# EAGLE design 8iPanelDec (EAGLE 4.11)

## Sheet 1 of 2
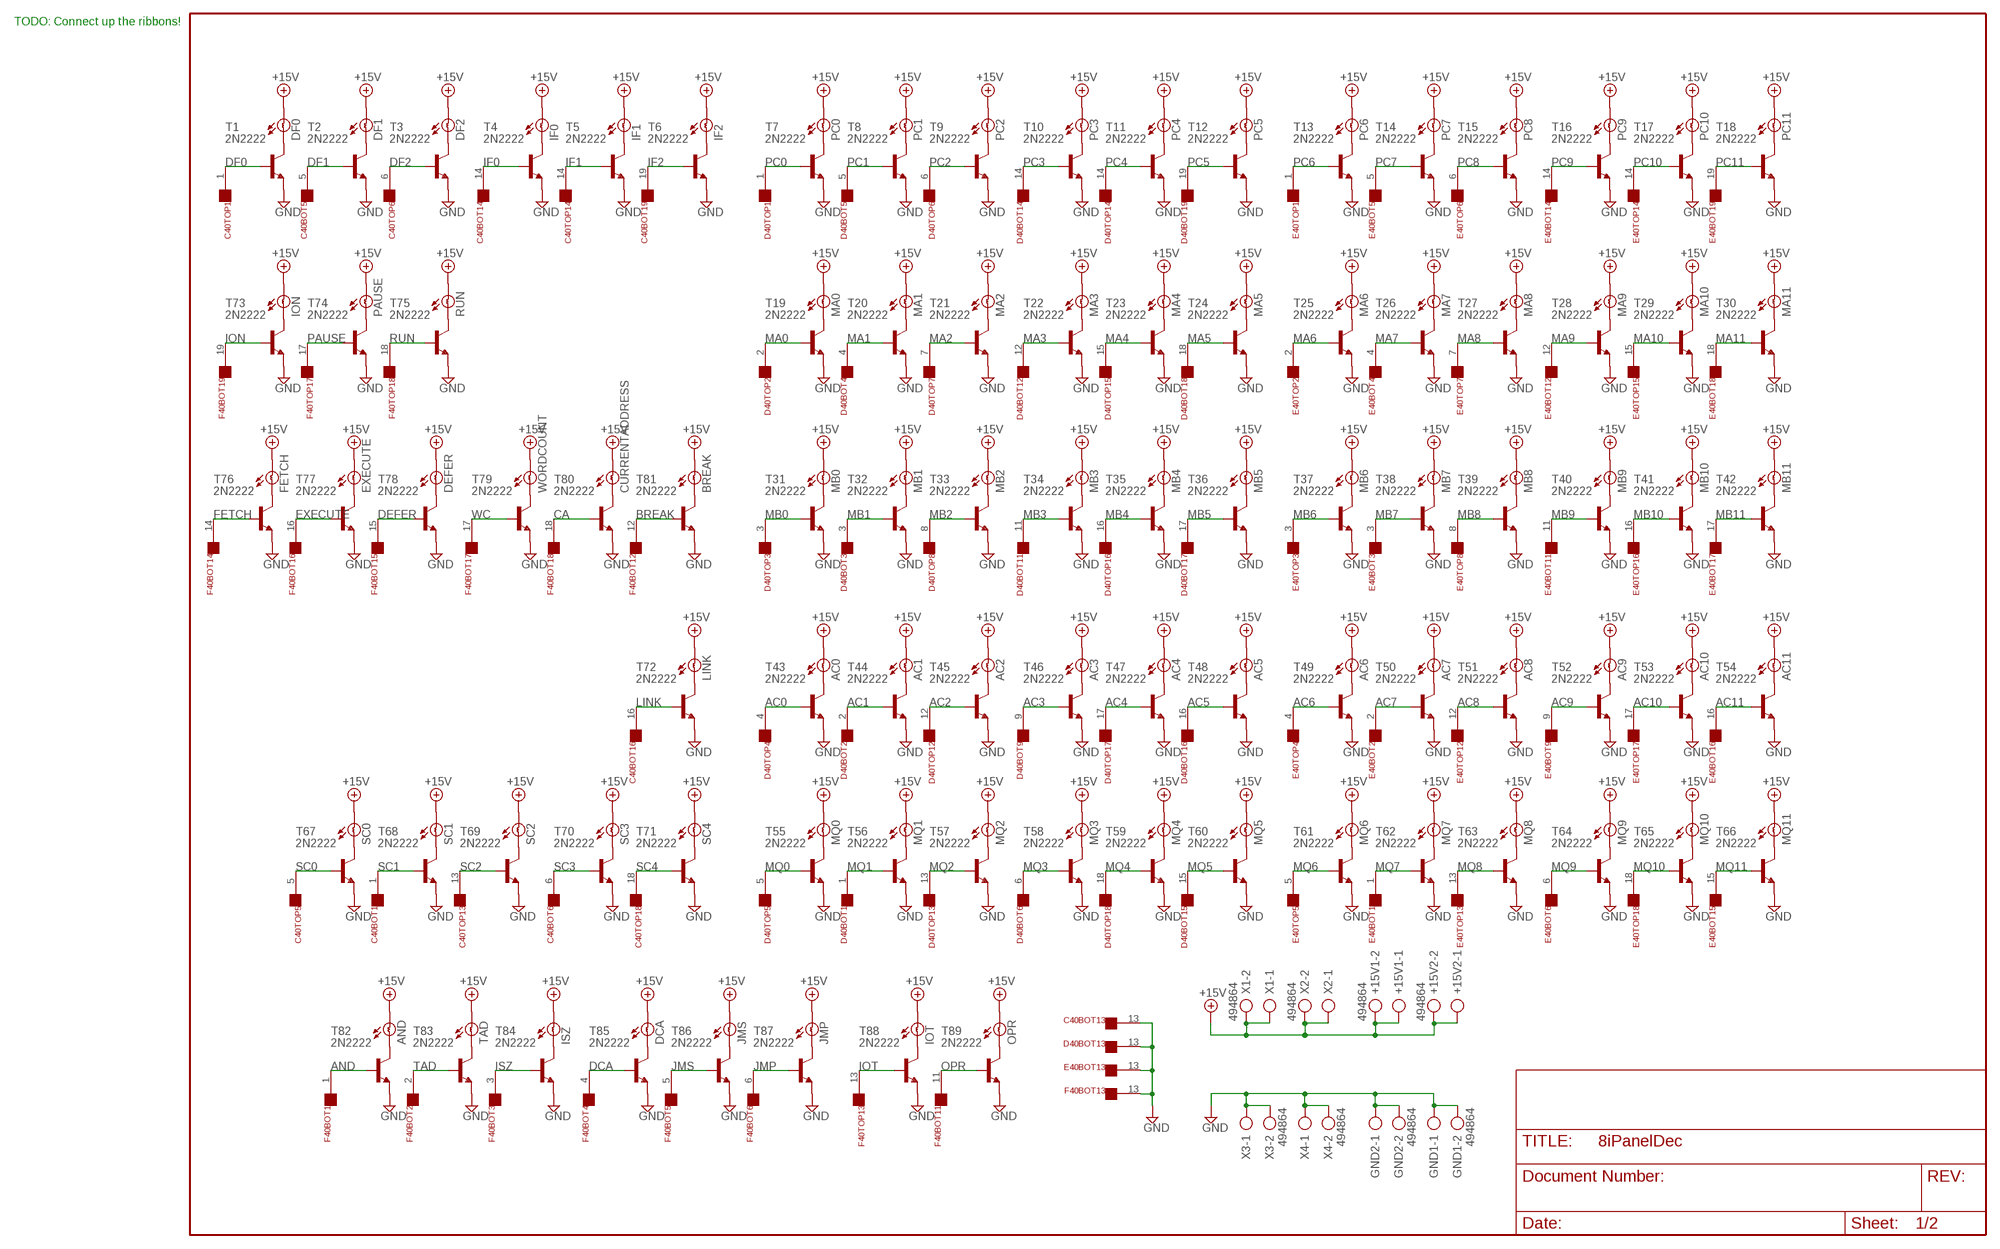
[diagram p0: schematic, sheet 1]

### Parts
+15V1  494864  AK500/2  [AK500/2]
+15V2  494864  AK500/2  [AK500/2]
AC0  BULB  [BULB]
AC1  BULB  [BULB]
AC2  BULB  [BULB]
AC3  BULB  [BULB]
AC4  BULB  [BULB]
AC5  BULB  [BULB]
AC6  BULB  [BULB]
AC7  BULB  [BULB]
AC8  BULB  [BULB]
AC9  BULB  [BULB]
AC10  BULB  [BULB]
AC11  BULB  [BULB]
AND  BULB  [BULB]
BREAK  BULB  [BULB]
C40BOT  FLEX19  [FLEX19]
C40TOP  FLEX19  [FLEX19]
CURRENTADDRESS  BULB  [BULB]
D40BOT  FLEX19  [FLEX19]
D40TOP  FLEX19  [FLEX19]
DCA  BULB  [BULB]
DEFER  BULB  [BULB]
DF0  BULB  [BULB]
DF1  BULB  [BULB]
DF2  BULB  [BULB]
E40BOT  FLEX19  [FLEX19]
E40TOP  FLEX19  [FLEX19]
EXECUTE  BULB  [BULB]
F40BOT  FLEX19  [FLEX19]
F40TOP  FLEX19  [FLEX19]
FETCH  BULB  [BULB]
GND1  494864  AK500/2  [AK500/2]
GND2  494864  AK500/2  [AK500/2]
IF0  BULB  [BULB]
IF1  BULB  [BULB]
IF2  BULB  [BULB]
ION  BULB  [BULB]
IOT  BULB  [BULB]
ISZ  BULB  [BULB]
JMP  BULB  [BULB]
JMS  BULB  [BULB]
LINK  BULB  [BULB]
MA0  BULB  [BULB]
MA1  BULB  [BULB]
MA2  BULB  [BULB]
MA3  BULB  [BULB]
MA4  BULB  [BULB]
MA5  BULB  [BULB]
MA6  BULB  [BULB]
MA7  BULB  [BULB]
MA8  BULB  [BULB]
MA9  BULB  [BULB]
MA10  BULB  [BULB]
MA11  BULB  [BULB]
MB0  BULB  [BULB]
MB1  BULB  [BULB]
MB2  BULB  [BULB]
MB3  BULB  [BULB]
MB4  BULB  [BULB]
MB5  BULB  [BULB]
MB6  BULB  [BULB]
MB7  BULB  [BULB]
MB8  BULB  [BULB]
MB9  BULB  [BULB]
MB10  BULB  [BULB]
MB11  BULB  [BULB]
MQ0  BULB  [BULB]
MQ1  BULB  [BULB]
MQ2  BULB  [BULB]
MQ3  BULB  [BULB]
MQ4  BULB  [BULB]
MQ5  BULB  [BULB]
MQ6  BULB  [BULB]
MQ7  BULB  [BULB]
MQ8  BULB  [BULB]
MQ9  BULB  [BULB]
MQ10  BULB  [BULB]
MQ11  BULB  [BULB]
OPR  BULB  [BULB]
PAUSE  BULB  [BULB]
PC0  BULB  [BULB]
PC1  BULB  [BULB]
PC2  BULB  [BULB]
PC3  BULB  [BULB]
PC4  BULB  [BULB]
PC5  BULB  [BULB]
PC6  BULB  [BULB]
PC7  BULB  [BULB]
PC8  BULB  [BULB]
PC9  BULB  [BULB]
PC10  BULB  [BULB]
PC11  BULB  [BULB]
RUN  BULB  [BULB]
SC0  BULB  [BULB]
SC1  BULB  [BULB]
SC2  BULB  [BULB]
SC3  BULB  [BULB]
SC4  BULB  [BULB]
T1  2N2222  -NPN-TO92  [TO92]
T2  2N2222  -NPN-TO92  [TO92]
T3  2N2222  -NPN-TO92  [TO92]
T4  2N2222  -NPN-TO92  [TO92]
T5  2N2222  -NPN-TO92  [TO92]
T6  2N2222  -NPN-TO92  [TO92]
T7  2N2222  -NPN-TO92  [TO92]
T8  2N2222  -NPN-TO92  [TO92]
T9  2N2222  -NPN-TO92  [TO92]
T10  2N2222  -NPN-TO92  [TO92]
T11  2N2222  -NPN-TO92  [TO92]
T12  2N2222  -NPN-TO92  [TO92]
T13  2N2222  -NPN-TO92  [TO92]
T14  2N2222  -NPN-TO92  [TO92]
T15  2N2222  -NPN-TO92  [TO92]
T16  2N2222  -NPN-TO92  [TO92]
T17  2N2222  -NPN-TO92  [TO92]
T18  2N2222  -NPN-TO92  [TO92]
T19  2N2222  -NPN-TO92  [TO92]
T20  2N2222  -NPN-TO92  [TO92]
T21  2N2222  -NPN-TO92  [TO92]
T22  2N2222  -NPN-TO92  [TO92]
T23  2N2222  -NPN-TO92  [TO92]
T24  2N2222  -NPN-TO92  [TO92]
T25  2N2222  -NPN-TO92  [TO92]
T26  2N2222  -NPN-TO92  [TO92]
T27  2N2222  -NPN-TO92  [TO92]
T28  2N2222  -NPN-TO92  [TO92]
T29  2N2222  -NPN-TO92  [TO92]
T30  2N2222  -NPN-TO92  [TO92]
T31  2N2222  -NPN-TO92  [TO92]
T32  2N2222  -NPN-TO92  [TO92]
T33  2N2222  -NPN-TO92  [TO92]
T34  2N2222  -NPN-TO92  [TO92]
T35  2N2222  -NPN-TO92  [TO92]
T36  2N2222  -NPN-TO92  [TO92]
T37  2N2222  -NPN-TO92  [TO92]
T38  2N2222  -NPN-TO92  [TO92]
T39  2N2222  -NPN-TO92  [TO92]
T40  2N2222  -NPN-TO92  [TO92]
T41  2N2222  -NPN-TO92  [TO92]
T42  2N2222  -NPN-TO92  [TO92]
T43  2N2222  -NPN-TO92  [TO92]
T44  2N2222  -NPN-TO92  [TO92]
T45  2N2222  -NPN-TO92  [TO92]
T46  2N2222  -NPN-TO92  [TO92]
T47  2N2222  -NPN-TO92  [TO92]
T48  2N2222  -NPN-TO92  [TO92]
T49  2N2222  -NPN-TO92  [TO92]
T50  2N2222  -NPN-TO92  [TO92]
T51  2N2222  -NPN-TO92  [TO92]
T52  2N2222  -NPN-TO92  [TO92]
T53  2N2222  -NPN-TO92  [TO92]
T54  2N2222  -NPN-TO92  [TO92]
T55  2N2222  -NPN-TO92  [TO92]
T56  2N2222  -NPN-TO92  [TO92]
T57  2N2222  -NPN-TO92  [TO92]
T58  2N2222  -NPN-TO92  [TO92]
T59  2N2222  -NPN-TO92  [TO92]
T60  2N2222  -NPN-TO92  [TO92]
T61  2N2222  -NPN-TO92  [TO92]
T62  2N2222  -NPN-TO92  [TO92]
T63  2N2222  -NPN-TO92  [TO92]
T64  2N2222  -NPN-TO92  [TO92]
T65  2N2222  -NPN-TO92  [TO92]
T66  2N2222  -NPN-TO92  [TO92]
T67  2N2222  -NPN-TO92  [TO92]
T68  2N2222  -NPN-TO92  [TO92]
T69  2N2222  -NPN-TO92  [TO92]
T70  2N2222  -NPN-TO92  [TO92]
T71  2N2222  -NPN-TO92  [TO92]
T72  2N2222  -NPN-TO92  [TO92]
T73  2N2222  -NPN-TO92  [TO92]
T74  2N2222  -NPN-TO92  [TO92]
T75  2N2222  -NPN-TO92  [TO92]
T76  2N2222  -NPN-TO92  [TO92]
T77  2N2222  -NPN-TO92  [TO92]
T78  2N2222  -NPN-TO92  [TO92]
T79  2N2222  -NPN-TO92  [TO92]
T80  2N2222  -NPN-TO92  [TO92]
T81  2N2222  -NPN-TO92  [TO92]
T82  2N2222  -NPN-TO92  [TO92]
T83  2N2222  -NPN-TO92  [TO92]
T84  2N2222  -NPN-TO92  [TO92]
T85  2N2222  -NPN-TO92  [TO92]
T86  2N2222  -NPN-TO92  [TO92]
T87  2N2222  -NPN-TO92  [TO92]
T88  2N2222  -NPN-TO92  [TO92]
T89  2N2222  -NPN-TO92  [TO92]
TAD  BULB  [BULB]
WORDCOUNT  BULB  [BULB]
X1  494864  AK500/2  [AK500/2]
X2  494864  AK500/2  [AK500/2]
X3  494864  AK500/2  [AK500/2]
X4  494864  AK500/2  [AK500/2]

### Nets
+15V [supply]: +15V1.1 +15V1.2 +15V2.1 +15V2.2 AC0.A AC1.A AC2.A AC3.A AC4.A AC5.A AC6.A AC7.A AC8.A AC9.A AC10.A AC11.A AND.A BREAK.A CURRENTADDRESS.A DCA.A DEFER.A DF0.A DF1.A DF2.A EXECUTE.A FETCH.A IF0.A IF1.A IF2.A ION.A IOT.A ISZ.A JMP.A JMS.A LINK.A MA0.A MA1.A MA2.A MA3.A MA4.A MA5.A MA6.A MA7.A MA8.A MA9.A MA10.A MA11.A MB0.A MB1.A MB2.A MB3.A MB4.A MB5.A MB6.A MB7.A MB8.A MB9.A MB10.A MB11.A MQ0.A MQ1.A MQ2.A MQ3.A MQ4.A MQ5.A MQ6.A MQ7.A MQ8.A MQ9.A MQ10.A MQ11.A OPR.A PAUSE.A PC0.A PC1.A PC2.A PC3.A PC4.A PC5.A PC6.A PC7.A PC8.A PC9.A PC10.A PC11.A RUN.A SC0.A SC1.A SC2.A SC3.A SC4.A TAD.A WORDCOUNT.A X1.1 X1.2 X2.1 X2.2
AC0: D40TOP.4 T43.2(B)
AC1: D40BOT.2 T44.2(B)
AC2: D40TOP.12 T45.2(B)
AC3: D40BOT.9 T46.2(B)
AC4: D40TOP.17 T47.2(B)
AC5: D40BOT.16 T48.2(B)
AC6: E40TOP.4 T49.2(B)
AC7: E40BOT.2 T50.2(B)
AC8: E40TOP.12 T51.2(B)
AC9: E40BOT.9 T52.2(B)
AC10: E40TOP.17 T53.2(B)
AC11: E40BOT.16 T54.2(B)
AND: F40BOT.1 T82.2(B)
BREAK: F40BOT.12 T81.2(B)
CA: F40BOT.18 T80.2(B)
DCA: F40BOT.4 T85.2(B)
DEFER: F40BOT.15 T78.2(B)
DF0: C40TOP.1 T1.2(B)
DF1: C40BOT.5 T2.2(B)
DF2: C40TOP.6 T3.2(B)
EXECUTE: F40BOT.16 T77.2(B)
FETCH: F40BOT.14 T76.2(B)
GND [supply]: C40BOT.13 D40BOT.13 E40BOT.13 F40BOT.13 GND1.1 GND1.2 GND2.1 GND2.2 T1.1(E) T2.1(E) T3.1(E) T4.1(E) T5.1(E) T6.1(E) T7.1(E) T8.1(E) T9.1(E) T10.1(E) T11.1(E) T12.1(E) T13.1(E) T14.1(E) T15.1(E) T16.1(E) T17.1(E) T18.1(E) T19.1(E) T20.1(E) T21.1(E) T22.1(E) T23.1(E) T24.1(E) T25.1(E) T26.1(E) T27.1(E) T28.1(E) T29.1(E) T30.1(E) T31.1(E) T32.1(E) T33.1(E) T34.1(E) T35.1(E) T36.1(E) T37.1(E) T38.1(E) T39.1(E) T40.1(E) T41.1(E) T42.1(E) T43.1(E) T44.1(E) T45.1(E) T46.1(E) T47.1(E) T48.1(E) T49.1(E) T50.1(E) T51.1(E) T52.1(E) T53.1(E) T54.1(E) T55.1(E) T56.1(E) T57.1(E) T58.1(E) T59.1(E) T60.1(E) T61.1(E) T62.1(E) T63.1(E) T64.1(E) T65.1(E) T66.1(E) T67.1(E) T68.1(E) T69.1(E) T70.1(E) T71.1(E) T72.1(E) T73.1(E) T74.1(E) T75.1(E) T76.1(E) T77.1(E) T78.1(E) T79.1(E) T80.1(E) T81.1(E) T82.1(E) T83.1(E) T84.1(E) T85.1(E) T86.1(E) T87.1(E) T88.1(E) T89.1(E) X3.1 X3.2 X4.1 X4.2
IF0: C40BOT.14 T4.2(B)
IF1: C40TOP.14 T5.2(B)
IF2: C40BOT.19 T6.2(B)
ION: F40BOT.19 T73.2(B)
IOT: F40TOP.13 T88.2(B)
ISZ: F40BOT.3 T84.2(B)
JMP: F40BOT.6 T87.2(B)
JMS: F40BOT.5 T86.2(B)
LINK: C40BOT.16 T72.2(B)
MA0: D40TOP.2 T19.2(B)
MA1: D40BOT.4 T20.2(B)
MA2: D40TOP.7 T21.2(B)
MA3: D40BOT.12 T22.2(B)
MA4: D40TOP.15 T23.2(B)
MA5: D40BOT.18 T24.2(B)
MA6: E40TOP.2 T25.2(B)
MA7: E40BOT.4 T26.2(B)
MA8: E40TOP.7 T27.2(B)
MA9: E40BOT.12 T28.2(B)
MA10: E40TOP.15 T29.2(B)
MA11: E40BOT.18 T30.2(B)
MB0: D40TOP.3 T31.2(B)
MB1: D40BOT.3 T32.2(B)
MB2: D40TOP.8 T33.2(B)
MB3: D40BOT.11 T34.2(B)
MB4: D40TOP.16 T35.2(B)
MB5: D40BOT.17 T36.2(B)
MB6: E40TOP.3 T37.2(B)
MB7: E40BOT.3 T38.2(B)
MB8: E40TOP.8 T39.2(B)
MB9: E40BOT.11 T40.2(B)
MB10: E40TOP.16 T41.2(B)
MB11: E40BOT.17 T42.2(B)
MQ0: D40TOP.5 T55.2(B)
MQ1: D40BOT.1 T56.2(B)
MQ2: D40TOP.13 T57.2(B)
MQ3: D40BOT.6 T58.2(B)
MQ4: D40TOP.18 T59.2(B)
MQ5: D40BOT.15 T60.2(B)
MQ6: E40TOP.5 T61.2(B)
MQ7: E40BOT.1 T62.2(B)
MQ8: E40TOP.13 T63.2(B)
MQ9: E40BOT.6 T64.2(B)
MQ10: E40TOP.18 T65.2(B)
MQ11: E40BOT.15 T66.2(B)
N$1: DF0.B T1.3(C)
N$2: DF1.B T2.3(C)
N$3: DF2.B T3.3(C)
N$4: IF0.B T4.3(C)
N$5: IF1.B T5.3(C)
N$6: IF2.B T6.3(C)
N$7: PC0.B T7.3(C)
N$8: PC1.B T8.3(C)
N$9: PC2.B T9.3(C)
N$10: PC3.B T10.3(C)
N$11: PC4.B T11.3(C)
N$12: PC5.B T12.3(C)
N$13: PC6.B T13.3(C)
N$14: PC7.B T14.3(C)
N$15: PC8.B T15.3(C)
N$16: PC9.B T16.3(C)
N$17: PC10.B T17.3(C)
N$18: PC11.B T18.3(C)
N$19: MA0.B T19.3(C)
N$20: MA1.B T20.3(C)
N$21: MA2.B T21.3(C)
N$22: MA3.B T22.3(C)
N$23: MA4.B T23.3(C)
N$24: MA5.B T24.3(C)
N$25: MA6.B T25.3(C)
N$26: MA7.B T26.3(C)
N$27: MA8.B T27.3(C)
N$28: MA9.B T28.3(C)
N$29: MA10.B T29.3(C)
N$30: MA11.B T30.3(C)
N$31: MB0.B T31.3(C)
N$32: MB1.B T32.3(C)
N$33: MB2.B T33.3(C)
N$34: MB3.B T34.3(C)
N$35: MB4.B T35.3(C)
N$36: MB5.B T36.3(C)
N$37: MB6.B T37.3(C)
N$38: MB7.B T38.3(C)
N$39: MB8.B T39.3(C)
N$40: MB9.B T40.3(C)
N$41: MB10.B T41.3(C)
N$42: MB11.B T42.3(C)
N$43: AC0.B T43.3(C)
N$44: AC1.B T44.3(C)
N$45: AC2.B T45.3(C)
N$46: AC3.B T46.3(C)
N$47: AC4.B T47.3(C)
N$48: AC5.B T48.3(C)
N$49: AC6.B T49.3(C)
N$50: AC7.B T50.3(C)
N$51: AC8.B T51.3(C)
N$52: AC9.B T52.3(C)
N$53: AC10.B T53.3(C)
N$54: AC11.B T54.3(C)
N$55: MQ0.B T55.3(C)
N$56: MQ1.B T56.3(C)
N$57: MQ2.B T57.3(C)
N$58: MQ3.B T58.3(C)
N$59: MQ4.B T59.3(C)
N$60: MQ5.B T60.3(C)
N$61: MQ6.B T61.3(C)
N$62: MQ7.B T62.3(C)
N$63: MQ8.B T63.3(C)
N$64: MQ9.B T64.3(C)
N$65: MQ10.B T65.3(C)
N$66: MQ11.B T66.3(C)
N$67: SC0.B T67.3(C)
N$68: SC1.B T68.3(C)
N$69: SC2.B T69.3(C)
N$70: SC3.B T70.3(C)
N$71: SC4.B T71.3(C)
N$72: LINK.B T72.3(C)
N$73: ION.B T73.3(C)
N$74: PAUSE.B T74.3(C)
N$75: RUN.B T75.3(C)
N$76: FETCH.B T76.3(C)
N$77: EXECUTE.B T77.3(C)
N$78: DEFER.B T78.3(C)
N$79: T79.3(C) WORDCOUNT.B
N$80: CURRENTADDRESS.B T80.3(C)
N$81: BREAK.B T81.3(C)
N$82: AND.B T82.3(C)
N$83: T83.3(C) TAD.B
N$84: ISZ.B T84.3(C)
N$85: DCA.B T85.3(C)
N$86: JMS.B T86.3(C)
N$87: JMP.B T87.3(C)
N$88: IOT.B T88.3(C)
N$89: OPR.B T89.3(C)
OPR: F40BOT.11 T89.2(B)
PAUSE: F40TOP.17 T74.2(B)
PC0: D40TOP.1 T7.2(B)
PC1: D40BOT.5 T8.2(B)
PC2: D40TOP.6 T9.2(B)
PC3: D40BOT.14 T10.2(B)
PC4: D40TOP.14 T11.2(B)
PC5: D40BOT.19 T12.2(B)
PC6: E40TOP.1 T13.2(B)
PC7: E40BOT.5 T14.2(B)
PC8: E40TOP.6 T15.2(B)
PC9: E40BOT.14 T16.2(B)
PC10: E40TOP.14 T17.2(B)
PC11: E40BOT.19 T18.2(B)
RUN: F40TOP.18 T75.2(B)
SC0: C40TOP.5 T67.2(B)
SC1: C40BOT.1 T68.2(B)
SC2: C40TOP.13 T69.2(B)
SC3: C40BOT.6 T70.2(B)
SC4: C40TOP.18 T71.2(B)
TAD: F40BOT.2 T83.2(B)
WC: F40BOT.17 T79.2(B)
Unconnected: C40BOT.2 C40BOT.3 C40BOT.4 C40BOT.7 C40BOT.8 C40BOT.9 C40BOT.10 C40BOT.11 C40BOT.12 C40BOT.15 C40BOT.17 C40BOT.18 C40TOP.2 C40TOP.3 C40TOP.4 C40TOP.7 C40TOP.8 C40TOP.9 C40TOP.10 C40TOP.11 C40TOP.12 C40TOP.15 C40TOP.16 C40TOP.17 C40TOP.19 D40BOT.7 D40BOT.8 D40BOT.10 D40TOP.9 D40TOP.10 D40TOP.11 D40TOP.19 E40BOT.7 E40BOT.8 E40BOT.10 E40TOP.9 E40TOP.10 E40TOP.11 E40TOP.19 F40BOT.7 F40BOT.8 F40BOT.9 F40BOT.10 F40TOP.1 F40TOP.2 F40TOP.3 F40TOP.4 F40TOP.5 F40TOP.6 F40TOP.7 F40TOP.8 F40TOP.9 F40TOP.10 F40TOP.11 F40TOP.12 F40TOP.14 F40TOP.15 F40TOP.16 F40TOP.19

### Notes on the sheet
- TODO: Connect up the ribbons!

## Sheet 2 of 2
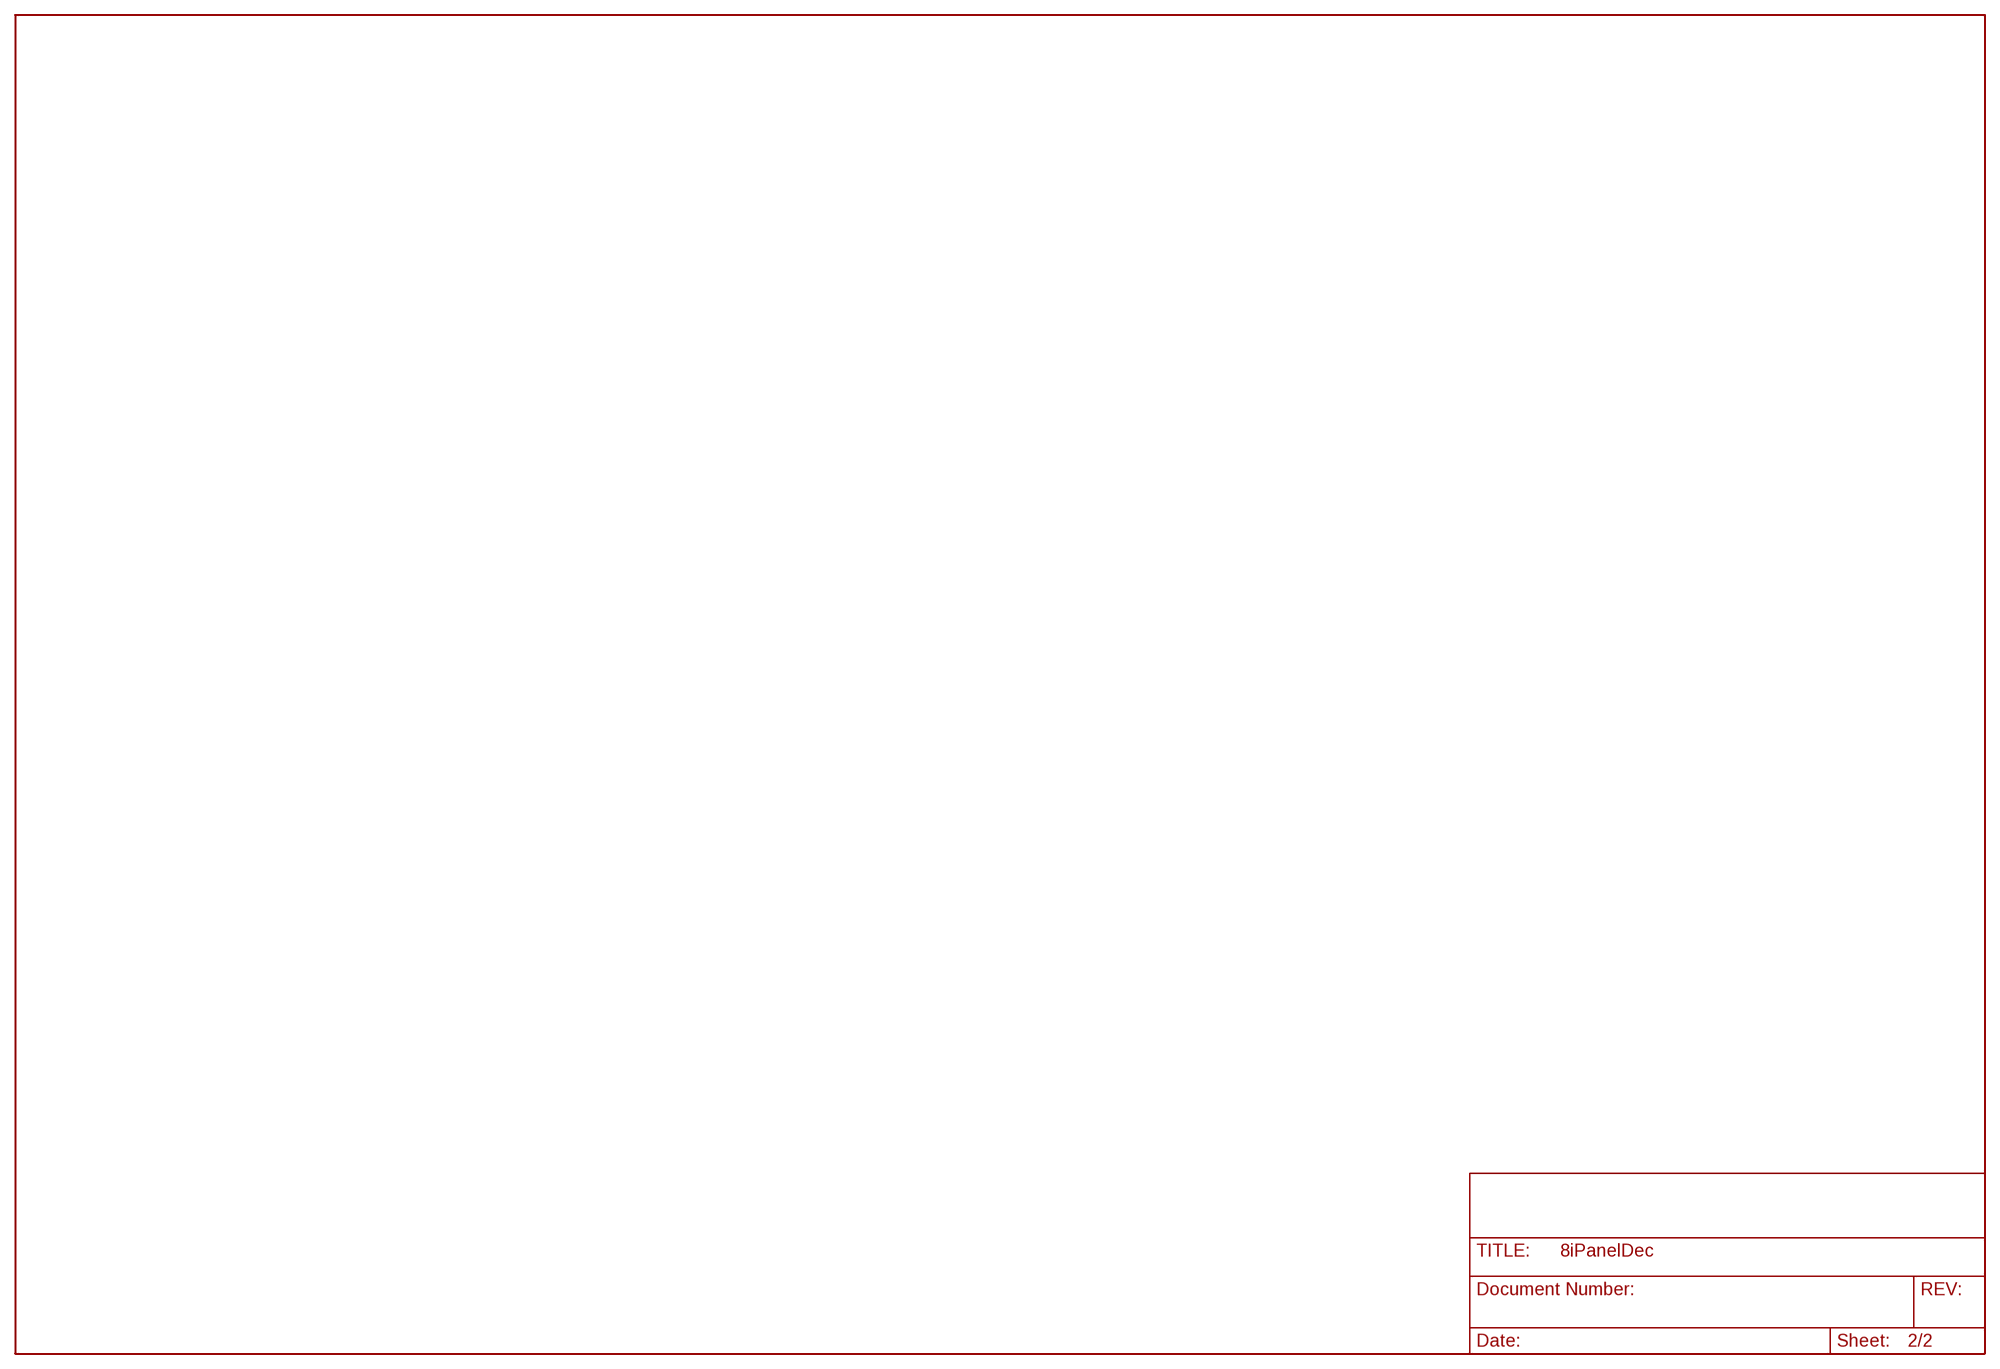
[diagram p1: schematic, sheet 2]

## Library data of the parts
+15V1 +15V2 GND1 GND2 X1-X4 = con-ptr500:AK500/2: CONNECTOR
AC0 AC1-AC11 AND BREAK CURRENTADDRESS DCA DEFER DF0 DF1 DF2 EXECUTE FETCH IF0 IF1 IF2 ION IOT ISZ JMP JMS LINK MA0 MA1-MA11 MB0 MB1-MB11 MQ0 MQ1-MQ11 OPR PAUSE PC0 PC1-PC11 RUN SC0 SC1-SC4 TAD WORDCOUNT = dec-con:BULB: LED
C40BOT C40TOP D40BOT D40TOP E40BOT E40TOP F40BOT F40TOP = dec-con:FLEX19
T1-T89 = transistor:*-NPN-: NPN Transistror

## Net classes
1 supply: width 0.762 mm

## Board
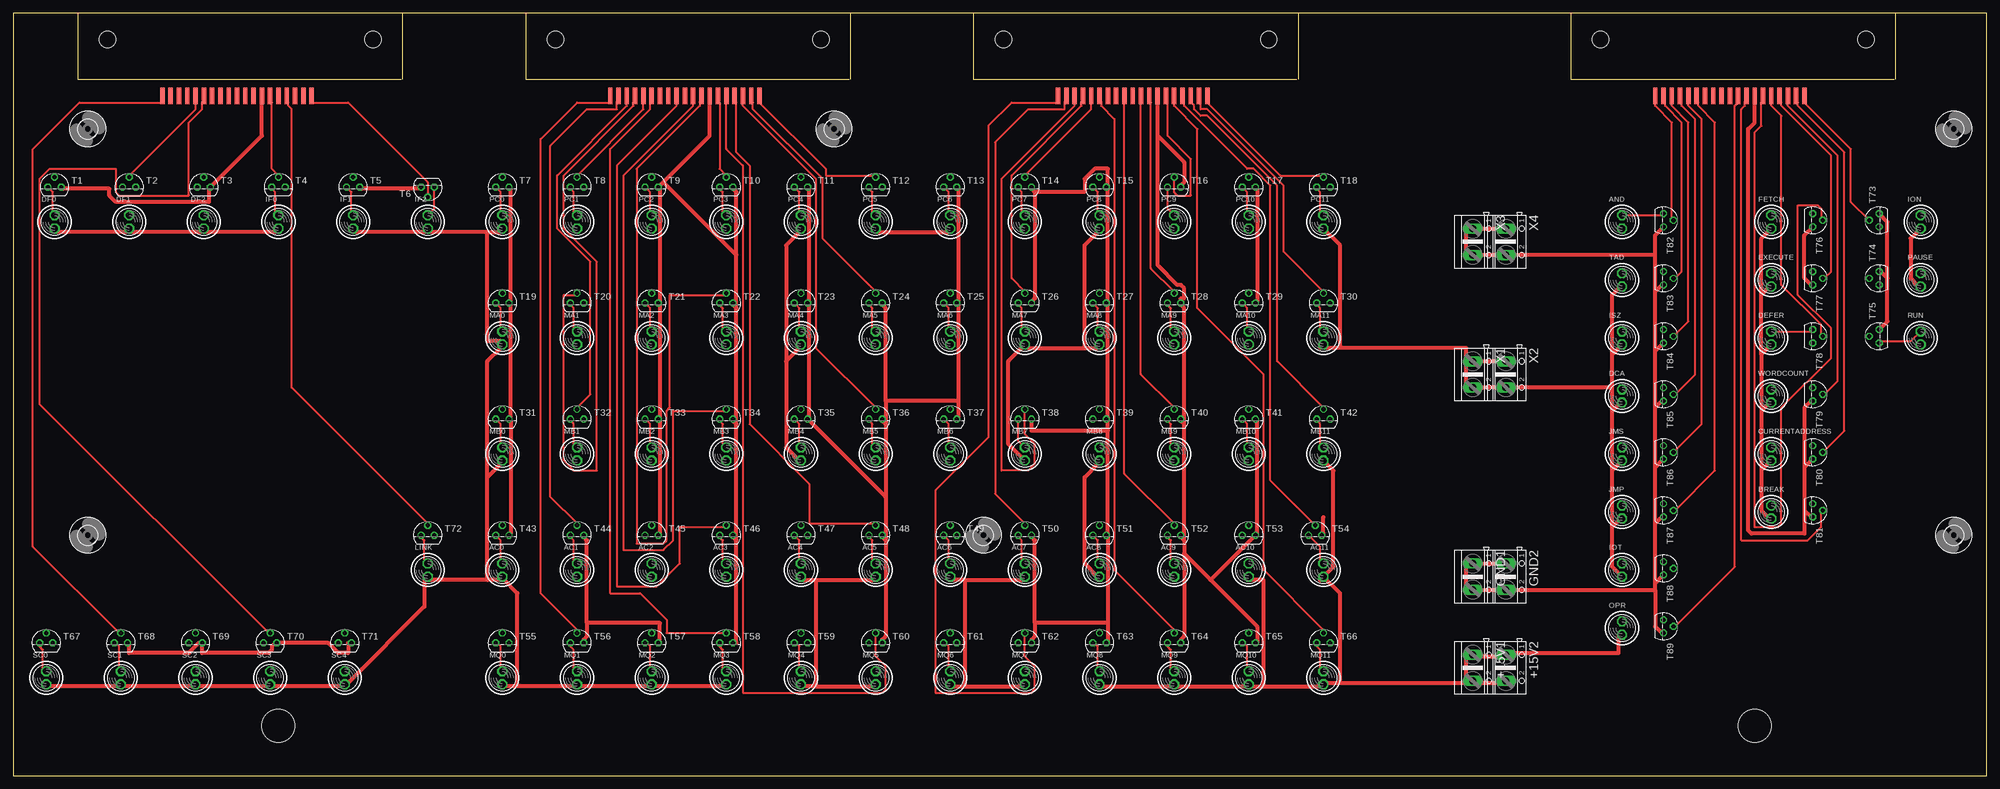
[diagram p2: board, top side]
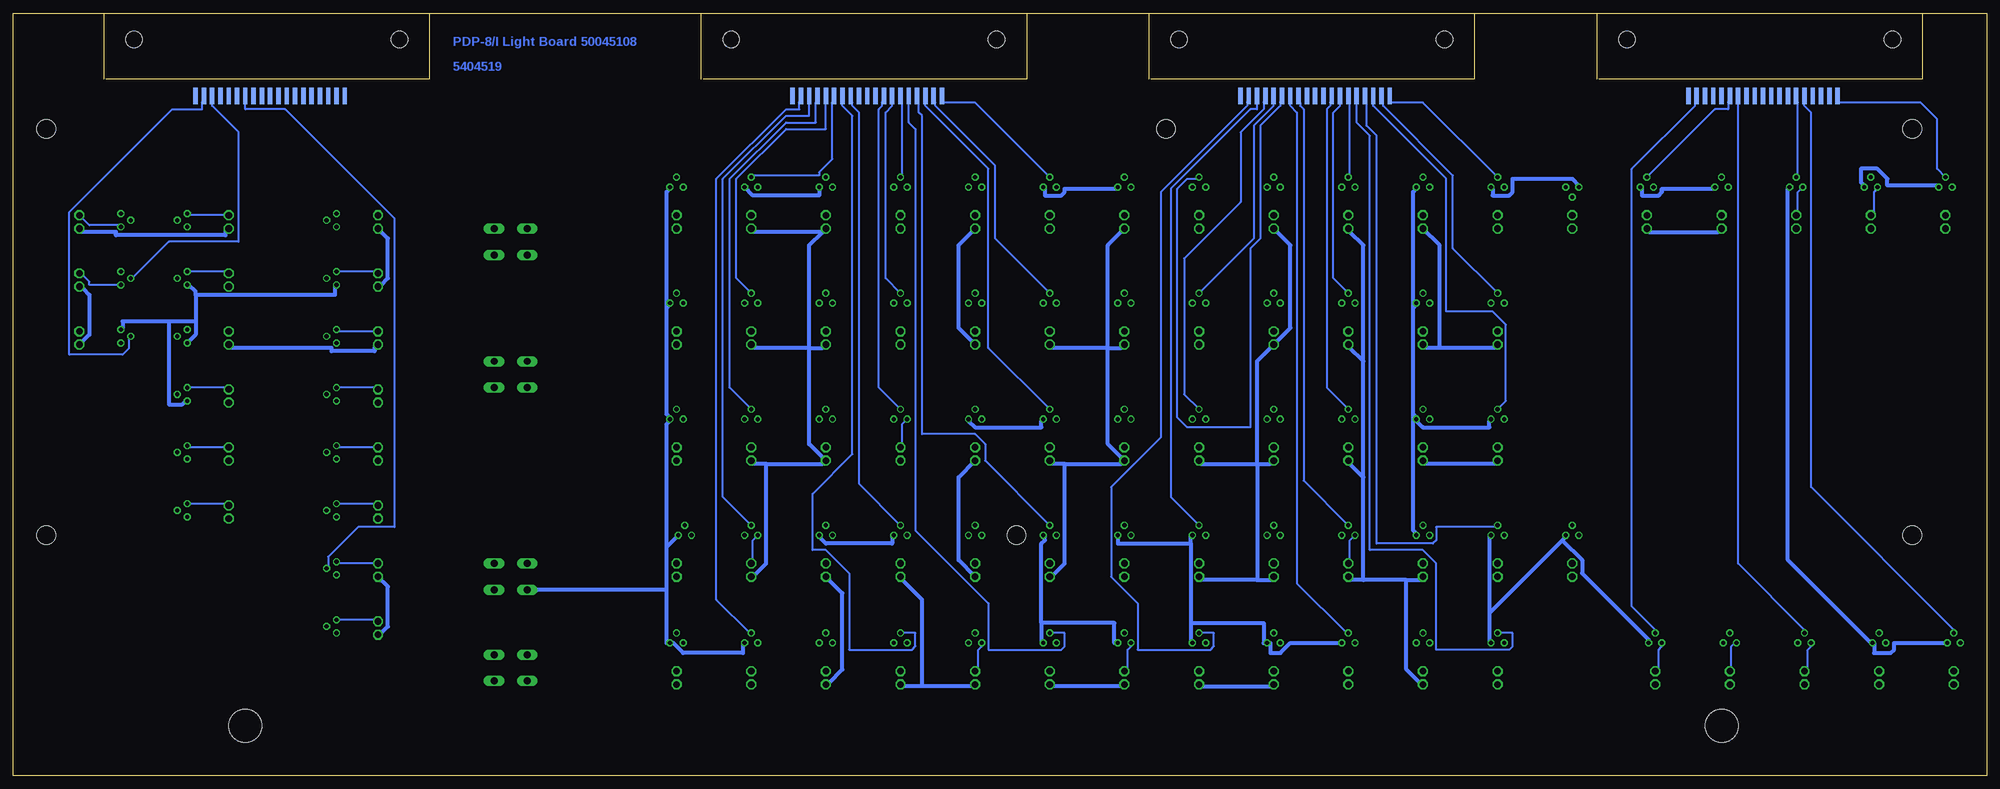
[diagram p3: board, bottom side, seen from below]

Size 377.82 x 146.05 mm. Coordinates in mm from the lower left corner, seen from the top.
Outline: 0,0 377.82,0 377.82,146.05 0,146.05 0,0
Copper layers (1*16): Top 0.035mm / dielectric 1.5mm / Bottom 0.035mm
Design rules "15mils": minimum track width 15mil, minimum drill 24mil, track to track 15mil, track to pad 10mil, pad to pad 10mil, via to via 10mil, smd to smd 10mil, copper to edge 25mil, drill to drill 10mil, minimum pad ring 10mil, minimum via ring 8mil, stop-mask expansion 0mil, vias tented up to drill 0mil, thermal gap 10mil
Holes 6.35 mm at 50.8,9.53 333.38,9.53

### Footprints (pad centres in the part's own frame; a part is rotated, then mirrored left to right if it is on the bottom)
AK500/2 = drill 1.321 long: 1 -2.515,0; 2 2.515,0
BULB = drill 1.27 octagon: A 0,0; B 0,2.54
FLEX19 = smd 3.175 x 0.838: 1 0,14.287; 2 0,12.7; 3 0,11.113; 4 0,9.525; 5 0,7.938; 6 0,6.35; 7 0,4.763; 8 0,3.175; 9 0,1.587; 10 0,0; 11 0,-1.587; 12 0,-3.175; 13 0,-4.763; 14 0,-6.35; 15 0,-7.938; 16 0,-9.525; 17 0,-11.113; 18 0,-12.7; 19 0,-14.287
TO92 = drill 0.813 octagon: 1 1.27,0; 2 0,1.905; 3 -1.27,0
STRAIN-RELIEF = hole 3.175: 7.62,56.515; 7.62,5.715
3,6 = hole 3.6: 0,0

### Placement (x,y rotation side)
+15V1  279.4,20.64 270 top
+15V2  285.75,20.64 270 top
AC0  93.66,38.1 0 top
AC1  107.95,38.1 0 top
AC2  122.24,38.1 0 top
AC3  136.53,38.1 0 top
AC4  150.81,38.1 0 top
AC5  165.1,38.1 0 top
AC6  179.39,38.1 0 top
AC7  193.68,38.1 0 top
AC8  207.96,38.1 0 top
AC9  222.25,38.1 0 top
AC10  236.54,38.1 0 top
AC11  250.82,38.1 0 top
AND  307.98,104.78 0 top
BREAK  336.55,49.21 0 top
C40BOT  42.86,130.18 90 top
C40TOP  42.86,130.18 270 bottom
CURRENTADDRESS  336.55,60.33 0 top
D40BOT  128.59,130.18 90 top
D40TOP  128.59,130.18 270 bottom
DCA  307.98,71.44 0 top
DEFER  336.55,82.55 0 top
DF0  7.94,104.78 0 top
DF1  22.23,104.78 0 top
DF2  36.51,104.78 0 top
E40BOT  214.31,130.18 90 top
E40TOP  214.31,130.18 270 bottom
EXECUTE  336.55,93.66 0 top
F40BOT  328.61,130.18 90 top
F40TOP  328.61,130.18 270 bottom
FETCH  336.55,104.78 0 top
GND1  279.4,38.1 270 top
GND2  285.75,38.1 270 top
IF0  50.8,104.78 0 top
IF1  65.09,104.78 0 top
IF2  79.38,104.78 0 top
ION  365.12,104.78 0 top
IOT  307.98,38.1 0 top
ISZ  307.98,82.55 0 top
JMP  307.98,49.21 0 top
JMS  307.98,60.33 0 top
LINK  79.38,38.1 0 top
MA0  93.66,82.55 0 top
MA1  107.95,82.55 0 top
MA2  122.24,82.55 0 top
MA3  136.53,82.55 0 top
MA4  150.81,82.55 0 top
MA5  165.1,82.55 0 top
MA6  179.39,82.55 0 top
MA7  193.68,82.55 0 top
MA8  207.96,82.55 0 top
MA9  222.25,82.55 0 top
MA10  236.54,82.55 0 top
MA11  250.82,82.55 0 top
MB0  93.66,60.33 0 top
MB1  107.95,60.33 0 top
MB2  122.24,60.33 0 top
MB3  136.53,60.33 0 top
MB4  150.81,60.33 0 top
MB5  165.1,60.33 0 top
MB6  179.39,60.33 0 top
MB7  193.68,60.33 0 top
MB8  207.96,60.33 0 top
MB9  222.25,60.33 0 top
MB10  236.54,60.33 0 top
MB11  250.82,60.33 0 top
MQ0  93.66,17.46 0 top
MQ1  107.95,17.46 0 top
MQ2  122.24,17.46 0 top
MQ3  136.53,17.46 0 top
MQ4  150.81,17.46 0 top
MQ5  165.1,17.46 0 top
MQ6  179.39,17.46 0 top
MQ7  193.68,17.46 0 top
MQ8  207.96,17.46 0 top
MQ9  222.25,17.46 0 top
MQ10  236.54,17.46 0 top
MQ11  250.82,17.46 0 top
OPR  307.98,26.99 0 top
PAUSE  365.12,93.66 0 top
PC0  93.66,104.78 0 top
PC1  107.95,104.78 0 top
PC2  122.24,104.78 0 top
PC3  136.53,104.78 0 top
PC4  150.81,104.78 0 top
PC5  165.1,104.78 0 top
PC6  179.39,104.78 0 top
PC7  193.68,104.78 0 top
PC8  207.96,104.78 0 top
PC9  222.25,104.78 0 top
PC10  236.54,104.78 0 top
PC11  250.82,104.78 0 top
RUN  365.12,82.55 0 top
SC0  6.35,17.46 0 top
SC1  20.64,17.46 0 top
SC2  34.92,17.46 0 top
SC3  49.21,17.46 0 top
SC4  63.5,17.46 0 top
T1  7.94,112.71 0 top
T2  22.23,112.71 0 top
T3  36.51,112.71 0 top
T4  50.8,112.71 0 top
T5  65.09,112.71 0 top
T6  79.38,112.71 180 top
T7  93.66,112.71 0 top
T8  107.95,112.71 0 top
T9  122.24,112.71 0 top
T10  136.53,112.71 0 top
T11  150.81,112.71 0 top
T12  165.1,112.71 0 top
T13  179.39,112.71 0 top
T14  193.68,112.71 0 top
T15  207.96,112.71 0 top
T16  222.25,112.71 0 top
T17  236.54,112.71 0 top
T18  250.82,112.71 0 top
T19  93.66,90.49 0 top
T20  107.95,90.49 0 top
T21  122.24,90.49 0 top
T22  136.53,90.49 0 top
T23  150.81,90.49 0 top
T24  165.1,90.49 0 top
T25  179.39,90.49 0 top
T26  193.68,90.49 0 top
T27  207.96,90.49 0 top
T28  222.25,90.49 0 top
T29  236.54,90.49 0 top
T30  250.82,90.49 0 top
T31  93.66,68.26 0 top
T32  107.95,68.26 0 top
T33  122.24,68.26 0 top
T34  136.53,68.26 0 top
T35  150.81,68.26 0 top
T36  165.1,68.26 0 top
T37  179.39,68.26 0 top
T38  193.68,68.26 0 top
T39  207.96,68.26 0 top
T40  222.25,68.26 0 top
T41  236.54,68.26 0 top
T42  250.82,68.26 0 top
T43  93.66,46.04 0 top
T44  107.95,46.04 0 top
T45  122.24,46.04 0 top
T46  136.53,46.04 0 top
T47  150.81,46.04 0 top
T48  165.1,46.04 0 top
T49  179.39,46.04 0 top
T50  193.68,46.04 0 top
T51  207.96,46.04 0 top
T52  222.25,46.04 0 top
T53  236.54,46.04 0 top
T54  249.24,46.04 0 top
T55  93.66,25.4 0 top
T56  107.95,25.4 0 top
T57  122.24,25.4 0 top
T58  136.53,25.4 0 top
T59  150.81,25.4 0 top
T60  165.1,25.4 0 top
T61  179.39,25.4 0 top
T62  193.68,25.4 0 top
T63  207.96,25.4 0 top
T64  222.25,25.4 0 top
T65  236.54,25.4 0 top
T66  250.82,25.4 0 top
T67  6.35,25.4 0 top
T68  20.64,25.4 0 top
T69  34.92,25.4 0 top
T70  49.21,25.4 0 top
T71  63.5,25.4 0 top
T72  79.38,46.04 0 top
T73  357.19,106.36 90 top
T74  357.19,95.25 90 top
T75  357.19,84.14 90 top
T76  344.49,106.36 270 top
T77  344.49,95.25 270 top
T78  344.49,84.14 270 top
T79  344.49,73.03 270 top
T80  344.49,61.91 270 top
T81  344.49,50.8 270 top
T82  315.91,106.36 270 top
T83  315.91,95.25 270 top
T84  315.91,84.14 270 top
T85  315.91,73.03 270 top
T86  315.91,61.91 270 top
T87  315.91,50.8 270 top
T88  315.91,39.69 270 top
T89  315.91,28.57 270 top
TAD  307.98,93.66 0 top
U$1  [STRAIN-RELIEF]  74.61,133.35 90 top
U$2  [STRAIN-RELIEF]  160.34,133.35 90 top
U$3  [STRAIN-RELIEF]  246.06,133.35 90 top
U$4  [STRAIN-RELIEF]  360.36,133.35 90 top
U$5  [3,6]  371.48,123.83 0 top
U$6  [3,6]  371.48,46.04 0 top
U$7  [3,6]  185.74,46.04 0 top
U$8  [3,6]  14.29,46.04 0 top
U$9  [3,6]  14.29,123.83 0 top
U$11  [3,6]  157.16,123.83 0 top
WORDCOUNT  336.55,71.44 0 top
X1  279.4,76.83 270 top
X2  285.75,76.83 270 top
X3  279.4,102.23 270 top
X4  285.75,102.23 270 top

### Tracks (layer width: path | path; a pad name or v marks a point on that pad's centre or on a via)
+15V
  Top 0.762: ION.A 363.22,102.87 363.22,95.25 364.49,93.98 PAUSE.A | 334.64,58.42 334.64,50.8 335.92,49.53 BREAK.A | 334.64,58.42 CURRENTADDRESS.A | 334.64,69.85 335.92,71.12 WORDCOUNT.A | 334.64,69.85 334.64,58.42 | 334.64,80.64 334.64,69.85 | DEFER.A 334.64,80.64 | 334.64,92.08 335.92,93.34 EXECUTE.A | 334.64,80.64 334.64,92.08 | 334.64,92.08 334.64,102.87 FETCH.A | 250.19,81.92 MA11.A 251.46,81.92 254,81.92 | MA10.A 236.85,81.92 | X1.1 281.31,79.38 283.85,79.38 X2.1 | X1.1 278.13,78.74 278.13,74.93 X1.2 281.31,74.3 283.85,74.3 X2.2 287.65,74.3 306.07,74.3 | +15V1.2 281.31,17.78 283.85,17.78 +15V2.2 | +15V1.2 278.13,19.05 278.13,22.23 +15V1.1 281.31,22.86 283.85,22.86 +15V2.1 287.65,23.5 307.34,23.5 307.34,26.67 OPR.A | 306.07,47.62 307.34,48.9 JMP.A | 306.07,47.62 306.07,40.01 IOT.A | 306.07,47.62 306.07,58.42 | 306.07,58.42 JMS.A | 306.07,69.85 307.34,71.12 DCA.A | 306.07,58.42 306.07,69.85 | 306.07,69.85 306.07,74.3 | 306.07,74.3 306.07,80.64 | 306.07,80.64 ISZ.A | 306.07,80.64 306.07,92.08 307.34,93.34 TAD.A | 254,81.92 278.13,81.92 278.13,80.01 X1.1 | DF0.A 8.26,104.14 21.59,104.14 DF1.A 22.86,104.14 36.2,104.14 DF2.A 36.83,104.14 50.16,104.14 IF0.A | IF1.A 65.41,104.14 78.74,104.14 IF2.A 80.01,104.14 90.81,104.14 | 90.81,104.14 93.34,104.14 PC0.A | 90.81,104.14 90.81,83.19 93.34,83.19 MA0.A 93.34,81.92 90.81,79.38 90.81,57.15 | PC5.A 165.74,104.14 179.07,104.14 PC6.A | 205.1,81.92 207.65,81.92 MA8.A | 205.1,81.92 194.31,81.92 MA7.A 190.5,79.38 190.5,63.5 MB7.A | 205.1,81.92 205.1,101.6 207.65,104.14 PC8.A | 182.25,37.47 193.04,37.47 AC7.A | 182.25,37.47 179.71,37.47 AC6.A | 147.96,79.38 150.5,81.92 MA4.A
  Top 0.762: 147.96,79.38 147.96,62.87 150.5,60.33 MB4.A | 147.96,79.38 147.96,101.6 150.5,104.14 PC4.A | SC0.A 6.99,17.14 20.32,17.14 SC1.A 20.95,17.14 34.29,17.14 SC2.A 35.56,17.14 48.9,17.14 SC3.A 49.53,17.14 62.87,17.14 SC4.A 64.14,17.78 78.74,32.38 78.74,37.47 LINK.A 80.01,37.47 90.81,37.47 | AC10.A 236.85,37.47 239.4,37.47 239.4,17.14 | AC11.A 250.19,37.47 | MB11.A 252.73,58.42 252.73,40.01 AC11.A | 153.67,37.47 151.13,37.47 AC4.A | 153.67,37.47 164.47,37.47 AC5.A | 90.81,37.47 93.34,37.47 AC0.A 93.98,37.47 96.52,34.92 96.52,17.14 | 96.52,17.14 107.31,17.14 MQ1.A 108.58,17.14 121.92,17.14 MQ2.A 122.56,17.14 135.89,17.14 MQ3.A | 96.52,17.14 93.98,17.14 MQ0.A | 153.67,17.14 151.13,17.14 MQ4.A | 153.67,17.14 164.47,17.14 MQ5.A | 182.25,17.14 179.71,17.14 MQ6.A | 182.25,17.14 193.04,17.14 MQ7.A | MB8.A 207.65,59.69 205.1,57.15 205.1,40.64 207.65,38.1 AC8.A | MQ8.A 208.28,17.14 221.62,17.14 MQ9.A 222.88,17.14 236.22,17.14 MQ10.A 236.85,17.14 239.4,17.14 | 239.4,17.14 250.19,17.14 MQ11.A 251.46,17.78 254,17.78 | 90.81,57.15 93.34,59.69 MB0.A | 90.81,37.47 90.81,57.15 | 153.67,37.47 153.67,17.14 | 182.25,17.14 182.25,37.47 | 254,17.78 277.5,17.78 +15V1.2 | 254,81.92 254,101.6 PC11.A | 254,17.78 254,34.92 AC11.A
  Bottom 0.762: RUN.A 363.22,84.45 363.22,92.08 364.49,93.34 PAUSE.A | ION.A 364.49,104.14 358.14,104.14 358.14,103.5 337.19,103.5 337.19,104.14 FETCH.A | 233.68,59.69 222.88,59.69 MB9.A 225.43,63.5 225.43,81.92 | 233.68,59.69 236.22,59.69 MB10.A | 225.43,81.92 236.22,81.92 MA10.A | 225.43,81.92 222.88,81.92 MA9.A | 225.43,81.92 225.43,101.6 222.88,104.14 | OPR.A 307.34,27.3 306.07,28.57 306.07,36.2 IOT.A | AND.A 306.07,102.87 306.07,95.25 307.34,93.98 TAD.A | DEFER.A 335.92,81.92 316.87,81.92 316.87,81.28 308.61,81.28 308.61,81.92 ISZ.A | 104.78,81.92 107.31,81.92 MA1.A | 104.78,81.92 93.98,81.92 MA0.A | 104.78,81.92 104.78,101.6 PC1.A | IF1.A 64.77,104.14 51.44,104.14 IF0.A | 176.53,59.69 179.07,59.69 MB6.A | 176.53,59.69 165.74,59.69 MB5.A 168.28,63.5 168.28,81.92 | 168.28,81.92 179.07,81.92 MA6.A | 168.28,81.92 165.74,81.92 MA5.A | 168.28,81.92 168.28,101.6 PC5.A | PC7.A 196.85,101.6 196.85,85.72 MA7.A | MB7.A 196.85,57.15 196.85,41.27 AC7.A | 176.53,59.69 176.53,40.64 179.07,38.1 AC6.A | 119.38,37.47 121.92,37.47 AC2.A | 111.12,37.47 119.38,37.47 | 111.12,37.47 108.58,37.47 AC1.A | 119.38,57.15 121.92,59.69 MB2.A | 119.38,37.47 119.38,57.15 | 119.38,79.38 121.92,81.92 MA2.A | 119.38,57.15 119.38,79.38 | 119.38,79.38 119.38,101.6 121.92,104.14 PC2.A | 139.7,59.69 150.5,59.69 MB4.A | 139.7,59.69 137.16,59.69 MB3.A | 139.7,59.69 139.7,79.38 MA3.A 133.35,85.72 133.35,101.6 PC3.A | 139.7,37.47 150.5,37.47 AC4.A | 139.7,37.47 137.16,37.47 AC3.A | MB0.A 93.98,59.69 107.31,59.69 MB1.A | MQ4.A 150.5,17.14 137.16,17.14 MQ3.A | MQ6.A 179.07,17.14 165.74,17.14 MQ5.A | 203.84,17.14 194.31,17.14 MQ7.A | 203.84,17.14 207.65,17.14 MQ8.A
  Bottom 0.762: 203.84,17.14 203.84,33.66 207.65,37.47 AC8.A | AC9.A 219.07,34.92 219.07,20.32 221.62,17.78 MQ9.A | 139.7,59.69 139.7,37.47 | 111.12,37.47 111.12,20.32 108.58,17.78 MQ1.A | 233.68,59.69 233.68,40.64 236.22,38.1 AC10.A | 222.88,104.14 236.22,104.14 PC10.A | 222.88,104.14 PC9.A
AC0
  Bottom 0.381: T43.2 93.98,47.62 105.41,47.62 105.41,45.09 106.05,44.45 116.84,44.45 116.84,122.56 118.75,124.46 118.75,128.91 D40TOP.4
AC1
  Top 0.381: T44.2 107.95,48.26 102.87,53.34 102.87,120.65 109.86,127.64 115.57,127.64 115.57,128.91 D40BOT.2
AC2
  Bottom 0.381: T45.2 130.81,56.52 130.81,127.64 131.44,128.27 131.44,128.91 D40TOP.12
AC3
  Top 0.381: T46.2 136.53,47.62 127.64,47.62 127.64,40.64 123.19,36.2 115.57,36.2 115.57,116.84 127,128.27 D40BOT.9
AC4
  Bottom 0.381: T47.2 156.21,53.34 156.21,112.39 140.97,127.64 139.7,127.64 D40TOP.17
AC5
  Top 0.381: T48.2 165.1,48.26 152.4,48.26 152.4,55.88 140.97,67.31 140.97,116.84 138.43,119.38 138.43,128.91 D40BOT.16
AC6
  Bottom 0.381: T49.2 191.77,60.33 191.77,63.5 193.68,65.41 203.84,65.41 203.84,126.36 204.47,127 204.47,128.91 E40TOP.4
AC7
  Top 0.381: T50.2 193.68,48.26 187.96,53.98 187.96,121.28 194.31,127.64 201.29,127.64 201.29,128.91 E40BOT.2
AC8
  Bottom 0.381: T51.2 215.9,55.88 215.9,127 217.17,128.27 217.17,128.91 E40TOP.12
AC9
  Top 0.381: T52.2 222.25,48.26 212.72,57.78 E40BOT.9
AC10
  Bottom 0.381: T53.2 241.94,53.34 241.94,114.3 229.87,126.36 225.43,126.36 E40TOP.17
AC11
  Top 0.381: T54.2 240.66,56.52 240.66,113.03 237.49,116.2 236.22,116.2 224.16,128.27 224.16,128.91 E40BOT.16
AND
  Top 0.381: T82.2 317.5,106.68 317.5,125.09 314.32,128.27 F40BOT.1
BREAK
  Top 0.381: T81.2 346.07,50.8 346.07,47.62 343.54,45.09 330.83,45.09 330.83,127.64 331.47,128.27 331.47,128.91 F40BOT.12
CA
  Top 0.381: T80.2 350.52,66.04 350.52,119.38 341.63,128.27 341.63,128.91 F40BOT.18
DCA
  Top 0.381: T85.2 318.13,73.03 321.94,76.83 321.94,125.73 319.4,128.27 319.4,128.91 F40BOT.4
DEFER
  Top 0.381: T78.2 346.07,84.45 346.07,86.36 338.45,93.98 338.45,126.36 336.55,128.27 F40BOT.15
DF0
  Bottom 0.381: T1.2 9.53,116.2 9.53,125.73 12.7,128.91 28.57,128.91 C40TOP.1
DF1
  Top 0.381: T2.2 22.23,114.94 34.92,127.64 C40BOT.5
DF2
  Bottom 0.381: T3.2 36.2,114.94 36.2,128.91 C40TOP.6
EXECUTE
  Top 0.381: T77.2 346.71,95.25 347.98,96.52 347.98,118.75 338.45,128.27 338.45,128.91 F40BOT.16
FETCH
  Top 0.381: T76.2 346.07,106.68 346.07,108.58 345.44,109.22 341.63,109.22 341.63,92.08 347.98,85.72 347.98,80.01 338.45,70.48 338.45,48.26 337.82,47.62 333.38,47.62 333.38,123.19 334.64,124.46 334.64,128.91 F40BOT.14
GND
  Top 0.762: 342.9,50.8 344.17,49.53 T81.1 | 342.9,59.05 342.9,50.8 | 342.9,59.05 T80.1 | 342.9,59.05 342.9,70.48 344.17,71.75 T79.1 | 342.9,50.8 342.9,46.35 332.74,46.35 332.11,46.99 332.11,123.83 333.38,125.09 F40BOT.13 | T76.1 342.9,103.5 342.9,95.25 344.17,93.98 T77.1 | 358.77,95.25 358.77,87 T75.1 | 358.77,95.25 357.5,96.52 T74.1 | 358.77,95.25 358.77,106.05 T73.1 | 314.32,35.56 314.32,28.57 315.6,27.3 T89.1 | 314.32,35.56 314.32,36.83 | 314.32,36.83 T88.1 | 314.32,48.26 315.6,49.53 T87.1 | 314.32,36.83 314.32,48.26 | 314.32,48.26 314.32,59.05 | 314.32,59.05 T86.1 | 314.32,70.48 315.6,71.75 T85.1 | 314.32,59.05 314.32,70.48 | 314.32,70.48 314.32,81.28 | 314.32,81.28 T84.1 | 314.32,92.71 315.6,93.98 T83.1 | 314.32,81.28 314.32,92.71 | 314.32,92.71 314.32,99.69 | 314.32,99.69 314.32,103.5 T82.1 | 219.07,122.56 224.16,117.47 224.16,113.67 223.52,113.03 T16.1 | 219.07,122.56 E40BOT.13 | T41.1 238.12,67.94 238.12,46.35 T53.1 229.24,37.47 | X4.1 283.85,104.78 281.31,104.78 X3.1 278.13,104.14 278.13,100.33 X3.2 281.31,99.69 283.85,99.69 X4.2 287.65,99.69 314.32,99.69 | GND2.1 283.85,40.64 281.31,40.64 GND1.1 278.13,40.01 278.13,36.2 GND1.2 281.31,35.56 283.85,35.56 GND2.2 287.65,35.56 314.32,35.56 | 224.16,45.09 224.16,42.55 | 224.16,42.55 224.16,26.67 223.52,26.04 T64.1 | 224.16,45.09 223.52,45.72 T52.1 | 224.16,67.31 223.52,67.94 T40.1 | 224.16,45.09 224.16,67.31 | 224.16,67.31 224.16,89.53 223.52,90.17 T28.1 223.52,91.44 224.16,91.44 224.16,93.34 223.52,93.98 222.88,93.98 219.07,97.79 219.07,122.56 | 224.16,42.55 229.24,37.47 | 229.24,37.47 238.12,28.57 238.12,25.4 T65.1 | 250.82,49.53 250.82,46.35 T54.1
  Top 0.762: 195.58,111.76 195.58,91.44 194.94,90.81 T26.1 | 195.58,111.76 194.94,112.39 T14.1 | 195.58,29.21 195.58,45.09 194.94,45.72 T50.1 | 195.58,29.21 195.58,26.67 194.94,26.04 T62.1 | 209.55,29.21 209.55,45.72 T51.1 209.55,46.35 209.55,66.04 | 209.55,29.21 209.55,25.4 T63.1 | 209.55,66.04 209.55,67.94 T39.1 209.55,68.58 209.55,90.17 T27.1 209.55,90.81 209.55,112.39 T15.1 209.55,113.03 209.55,116.2 207.01,116.2 205.1,114.3 205.1,111.76 195.58,111.76 | 209.55,29.21 195.58,29.21 | 180.97,71.75 180.97,90.17 T25.1 180.97,90.81 180.97,112.39 T13.1 | 180.97,71.75 180.97,68.58 T37.1 | T11.1 152.4,112.39 152.4,90.81 T23.1 152.4,90.17 152.4,68.58 T35.1 167,53.34 | 167,45.09 167,26.67 166.37,26.04 T60.1 | 167,45.09 166.37,45.72 T48.1 | 167,67.31 166.37,67.94 T36.1 | 167,53.34 167,45.09 | 167,67.31 167,53.34 | 167,71.75 167,67.31 | 167,71.75 167,89.53 166.37,90.17 T24.1 | 180.97,71.75 167,71.75 | 209.55,66.04 194.94,66.04 T38.1 | T45.1 123.83,46.35 123.83,67.94 T33.1 123.83,68.58 123.83,90.17 T21.1 123.83,90.81 123.83,112.39 T9.1 124.46,113.67 | 124.46,113.67 133.35,122.56 D40BOT.13 | 109.86,29.21 109.86,45.09 109.22,45.72 T44.1 | 109.86,29.21 109.86,26.67 109.22,26.04 T56.1 | 138.43,45.09 137.79,45.72 T46.1 | 138.43,45.09 138.43,25.4 T58.1 | 138.43,67.31 137.79,67.94 T34.1 | 138.43,45.09 138.43,67.31 | 138.43,89.53 137.79,90.17 T22.1 | 138.43,67.31 138.43,89.53 | 138.43,89.53 138.43,99.69 | 138.43,99.69 138.43,111.76 137.79,112.39 T10.1 | 109.86,29.21 123.83,29.21 123.83,25.4 T57.1 | 138.43,99.69 124.46,113.67 | C40BOT.13 47.62,122.56 T3.1 37.47,112.39 37.47,109.86 19.68,109.86 18.41,111.12 18.41,112.39 9.53,112.39 T1.1
  Top 0.762: T71.1 64.14,25.4 64.14,23.5 62.23,23.5 60.33,25.4 T70.1 50.16,25.4 49.53,24.77 49.53,24.13 48.9,23.5 36.2,23.5 T69.1 35.56,25.4 33.66,23.5 22.23,23.5 22.23,25.4 T68.1 | T6.1 78.11,112.39 66.67,112.39 T5.1 | T43.1 95.25,46.35 95.25,67.94 T31.1 95.25,68.58 95.25,90.17 T19.1 95.25,90.81 95.25,112.39 T7.1 | T29.1 238.12,90.81 238.12,112.39 T17.1
  Bottom 0.762: 342.9,92.08 342.9,92.71 344.17,93.98 T77.1 | 342.9,92.08 342.9,87 | 342.9,87 342.9,84.45 T78.1 | 347.98,87 356.87,87 356.87,85.72 T75.1 | 342.9,87 347.98,87 | 342.9,92.08 316.23,92.08 316.23,93.98 T83.1 | 347.98,87 347.98,71.12 345.44,71.12 344.81,71.75 T79.1 | T65.1 238.12,25.4 238.12,23.5 249.56,23.5 251.46,25.4 T66.1 252.73,25.4 252.73,35.56 | T12.1 166.37,112.39 176.53,112.39 176.53,111.76 177.16,111.12 180.34,111.12 180.34,112.39 T13.1 | T38.1 194.94,67.94 193.68,66.67 180.97,66.67 180.97,67.94 T37.1 | 180.97,29.21 180.97,44.45 180.34,45.09 180.34,45.72 T49.1 | 180.97,29.21 180.97,25.4 T61.1 | 152.4,44.45 152.4,45.72 T47.1 | 152.4,44.45 152.4,29.21 | 152.4,29.21 152.4,25.4 T59.1 | 152.4,44.45 166.37,44.45 T48.1 | 180.97,29.21 167,29.21 167,25.4 T60.1 | T57.1 133.35,25.4 135.25,23.5 137.16,23.5 137.16,25.4 T58.1 138.43,25.4 138.43,29.21 152.4,29.21 | T1.1 9.53,113.03 19.05,113.03 19.05,114.3 20.95,116.2 24.13,116.2 24.13,113.67 23.5,113.03 T2.1 | T67.1 17.78,25.4 17.78,24.13 18.41,23.5 21.59,23.5 21.59,25.4 T68.1 22.23,25.4 38.1,41.27 38.1,112.39 T3.1 | T4.1 52.07,112.39 62.23,112.39 62.23,111.76 62.87,111.12 66.04,111.12 66.04,112.39 T5.1 | 95.25,31.11 95.25,45.72 T43.1 | 95.25,31.11 95.25,25.4 T55.1 | 95.25,31.11 81.28,45.09 | 81.28,45.09 80.64,45.72 T72.1 | T31.1 95.25,67.94 95.25,66.67 107.95,66.67 109.22,67.94 T32.1 109.22,68.58 109.86,69.22 | 109.86,89.53 109.22,90.17 T20.1 | 109.86,69.22 109.86,89.53 | 109.86,89.53 109.86,111.76 109.22,112.39 T8.1 | T6.1 78.11,113.03 79.38,114.3 90.81,114.3 90.81,111.76 91.44,111.12 94.61,111.12 94.61,112.39 T7.1 | 81.28,45.09 77.47,41.27 77.47,38.73 64.77,26.04 T71.1
  Bottom 0.762: 109.86,69.22 109.86,46.99 109.22,46.35 T44.1 | T52.1 223.52,45.72 222.25,44.45 209.55,44.45 209.55,45.72 T51.1 | 252.73,89.53 252.73,69.22 252.09,68.58 T42.1 252.09,67.94 252.73,67.31 252.73,43.81 | 252.73,89.53 252.09,90.17 T30.1 | 252.73,89.53 252.73,111.76 252.09,112.39 T18.1 | 252.73,35.56 252.73,43.81 | 252.73,43.81 T54.1 | 252.73,35.56 277.5,35.56 GND1.2 | T17.1 236.22,111.12 223.52,111.12 T16.1
IF0
  Top 0.381: T4.2 50.8,114.94 49.53,116.2 49.53,128.91 C40BOT.14
IF1
  Bottom 0.381: T5.2 52.07,127.64 49.53,127.64 49.53,128.91 C40TOP.14
IF2
  Top 0.381: T6.2 79.38,113.67 64.14,128.91 57.15,128.91 C40BOT.19
ION
  Top 0.381: T73.2 351.79,109.86 351.79,120.02 342.9,128.91 F40BOT.19
IOT
  Bottom 0.381: T88.2 317.5,40.01 317.5,41.91 311.79,47.62 304.8,47.62 304.8,106.68 325.75,127.64 333.38,127.64 F40TOP.13
ISZ
  Top 0.381: T84.2 320.68,87 320.68,125.09 317.5,128.27 F40BOT.3
JMP
  Top 0.381: T87.2 318.13,50.8 325.75,58.42 325.75,125.09 322.58,128.27 322.58,128.91 F40BOT.6
JMS
  Top 0.381: T86.2 323.21,67.31 323.21,125.73 320.68,128.27 F40BOT.5
LINK
  Top 0.381: T72.2 79.38,48.26 53.34,74.3 53.34,127.64 52.7,128.27 52.7,128.91 C40BOT.16
MA0
  Bottom 0.381: T19.2 102.23,100.97 102.23,114.94 115.57,128.27 115.57,128.91 D40TOP.2
MA1
  Top 0.381: T20.2 107.95,92.08 105.41,92.08 105.41,60.33 107.31,58.42 111.76,58.42 111.76,98.42 105.41,104.78 105.41,114.94 118.75,128.27 118.75,128.91 D40BOT.4
MA2
  Bottom 0.381: T21.2 125.09,95.25 125.09,127 123.83,128.27 D40TOP.7
MA3
  Top 0.381: T22.2 136.53,92.08 125.73,92.08 125.73,70.48 125.09,69.85 125.09,45.09 124.46,44.45 119.38,44.45 119.38,116.2 131.44,128.27 131.44,128.91 D40BOT.12
MA4
  Bottom 0.381: T23.2 140.34,102.87 140.34,124.46 136.53,128.27 D40TOP.15
MA5
  Top 0.381: T24.2 165.1,92.71 154.94,102.87 154.94,114.3 141.6,127.64 141.6,128.91 D40BOT.18
MA6
  Bottom 0.381: T25.2 189.87,102.87 189.87,116.84 201.29,128.27 201.29,128.91 E40TOP.2
MA7
  Top 0.381: T26.2 193.68,92.71 191.13,95.25 191.13,114.94 204.47,128.27 204.47,128.91 E40BOT.4
MA8
  Bottom 0.381: T27.2 210.82,95.25 210.82,127 209.55,128.27 E40TOP.7
MA9
  Top 0.381: T28.2 222.25,92.71 217.81,97.16 217.81,128.91 E40BOT.12
MA10
  Bottom 0.381: T29.2 239.4,95.25 239.4,114.3 229.87,123.83 222.25,123.83 E40TOP.15
MA11
  Top 0.381: T30.2 250.82,92.71 243.21,100.33 243.21,113.03 228.6,127.64 227.33,127.64 227.33,128.91 E40BOT.18
MB0
  Bottom 0.381: T31.2 92.08,71.75 92.08,86.36 94.61,88.9 103.5,88.9 103.5,114.3 117.47,128.27 D40TOP.3
MB1
  Top 0.381: T32.2 107.95,70.48 110.49,73.03 110.49,98.42 104.14,104.78 104.14,114.94 117.47,128.27 D40BOT.3
MB2
  Bottom 0.381: T33.2 126.36,74.3 126.36,127.64 125.73,128.27 125.73,128.91 D40TOP.8
MB3
  Top 0.381: T34.2 136.53,69.85 126.36,69.85 126.36,45.09 124.46,43.18 116.84,43.18 116.84,114.94 130.18,128.27 D40BOT.11
MB4
  Bottom 0.381: T35.2 153.67,73.03 153.67,99.06 142.88,109.86 142.88,123.19 138.43,127.64 138.43,128.91 D40TOP.16
MB5
  Top 0.381: T36.2 165.1,70.48 153.67,81.92 153.67,114.3 139.7,128.27 D40BOT.17
MB6
  Bottom 0.381: T37.2 191.13,81.92 191.13,116.2 203.2,128.27 E40TOP.3
MB7
  Top 0.381: T38.2 193.68,65.41 195.58,63.5 195.58,59.69 194.31,58.42 189.23,58.42 189.23,114.3 203.2,128.27 E40BOT.3
MB8
  Bottom 0.381: T39.2 212.09,74.3 212.09,127.64 211.46,128.27 211.46,128.91 E40TOP.8
MB9
  Top 0.381: T40.2 222.25,70.48 215.9,76.83 E40BOT.11
MB10
  Bottom 0.381: T41.2 240.66,74.3 240.66,114.3 229.87,125.09 224.16,125.09 224.16,128.91 E40TOP.16
MB11
  Top 0.381: T42.2 250.82,70.48 241.94,79.38 241.94,113.03 228.6,126.36 227.33,126.36 226.06,127.64 226.06,128.27 225.43,128.91 E40BOT.17
MQ0
  Bottom 0.381: T55.2 90.81,27.3 90.81,24.77 91.44,24.13 105.41,24.13 105.41,40.64 107.95,43.18 118.11,43.18 118.11,122.56 120.65,125.09 D40TOP.5
MQ1
  Top 0.381: T56.2 107.95,27.94 100.97,34.92 100.97,121.92 107.95,128.91 114.3,128.91 D40BOT.1
MQ2
  Bottom 0.381: T57.2 122.56,27.3 132.08,36.83 132.08,127 133.35,128.27 D40TOP.13
MQ3
  Top 0.381: T58.2 125.09,27.3 125.09,29.84 120.02,34.92 114.3,34.92 114.3,120.02 121.92,127.64 121.92,128.91 D40BOT.6
MQ4
  Bottom 0.381: T59.2 147.96,27.3 147.96,24.77 148.59,24.13 162.56,24.13 162.56,33.02 167.64,38.1 167.64,55.24 158.12,64.77 158.12,111.76 141.6,128.27 141.6,128.91 D40TOP.18
MQ5
  Top 0.381: T60.2 165.1,22.86 167,20.95 167,16.51 166.37,15.88 139.7,15.88 139.7,116.84 136.53,120.02 D40BOT.15
MQ6
  Bottom 0.381: T61.2 176.53,27.3 176.53,24.77 177.16,24.13 191.13,24.13 191.13,33.02 205.1,46.99 205.1,123.83 206.38,125.09 E40TOP.5
MQ7
  Top 0.381: T62.2 193.68,22.86 195.58,20.95 195.58,16.51 194.94,15.88 176.53,15.88 176.53,54.61 186.69,64.77 186.69,124.46 191.13,128.91 200.03,128.91 E40BOT.1
MQ8
  Bottom 0.381: T63.2 205.1,27.3 205.1,24.77 205.74,24.13 217.81,24.13 217.81,38.73 222.25,43.18 224.79,43.18 224.79,53.98 217.17,61.59 217.17,126.36 219.07,128.27 E40TOP.13
MQ9
  Top 0.381: T64.2 222.25,27.94 210.82,39.37 210.82,125.73 208.28,128.27 208.28,128.91 E40BOT.6
MQ10
  Bottom 0.381: T65.2 236.85,27.3 243.21,33.66 243.21,114.3 229.87,127.64 227.33,127.64 227.33,128.91 E40TOP.18
MQ11
  Top 0.381: T66.2 250.82,27.94 239.4,39.37 239.4,76.83 226.69,89.53 226.69,123.83 222.25,128.27 E40BOT.15
N$1
  Top 0.381: T1.3 7.62,111.76 7.62,107.95 DF0.B
N$2
  Bottom 0.381: T2.3 20.95,112.39 21.59,111.76 21.59,107.95 DF1.B
N$3
  Bottom 0.381: T3.3 36.2,111.76 36.2,107.95 DF2.B
N$4
  Top 0.381: T4.3 49.53,112.39 50.16,111.76 50.16,107.95 IF0.B
N$5
  Top 0.381: T5.3 64.77,111.76 64.77,107.95 IF1.B
N$6
  Top 0.381: T6.3 80.64,108.58 IF2.B
N$7
  Top 0.381: T7.3 93.34,111.76 93.34,107.95 PC0.B
N$8
  Top 0.381: T8.3 106.68,112.39 107.31,111.76 107.31,107.95 PC1.B
N$9
  Top 0.381: T9.3 121.92,111.76 121.92,107.95 PC2.B
N$10
  Top 0.381: T10.3 135.25,112.39 135.89,111.76 135.89,107.95 PC3.B
N$11
  Top 0.381: T11.3 150.5,111.76 150.5,107.95 PC4.B
N$12
  Top 0.381: T12.3 163.83,112.39 164.47,111.76 164.47,107.95 PC5.B
N$13
  Top 0.381: T13.3 179.07,111.76 179.07,107.95 PC6.B
N$14
  Top 0.381: T14.3 192.41,112.39 193.04,111.76 193.04,107.95 PC7.B
N$15
  Top 0.381: T15.3 207.65,111.76 207.65,107.95 PC8.B
N$16
  Top 0.381: T16.3 220.98,108.58 PC9.B
N$17
  Top 0.381: T17.3 236.22,111.76 236.22,107.95 PC10.B
N$18
  Top 0.381: T18.3 249.56,112.39 250.19,111.76 250.19,107.95 PC11.B
N$19
  Top 0.381: T19.3 93.34,89.53 93.34,85.72 MA0.B
N$20
  Top 0.381: T20.3 106.68,90.17 107.31,89.53 107.31,85.72 MA1.B
N$21
  Top 0.381: T21.3 121.92,89.53 121.92,85.72 MA2.B
N$22
  Top 0.381: T22.3 135.25,90.17 135.89,89.53 135.89,85.72 MA3.B
N$23
  Top 0.381: T23.3 150.5,89.53 150.5,85.72 MA4.B
N$24
  Top 0.381: T24.3 163.83,90.17 164.47,89.53 164.47,85.72 MA5.B
N$25
  Top 0.381: T25.3 179.07,89.53 179.07,85.72 MA6.B
N$26
  Top 0.381: T26.3 192.41,90.17 193.04,89.53 193.04,85.72 MA7.B
N$27
  Top 0.381: T27.3 207.65,89.53 207.65,85.72 MA8.B
N$28
  Top 0.381: T28.3 220.98,90.17 221.62,89.53 221.62,85.72 MA9.B
N$29
  Top 0.381: T29.3 236.22,89.53 236.22,85.72 MA10.B
N$30
  Top 0.381: T30.3 249.56,90.17 250.19,89.53 250.19,85.72 MA11.B
N$31
  Top 0.381: T31.3 93.34,67.31 93.34,63.5 MB0.B
N$32
  Top 0.381: T32.3 106.68,67.94 107.31,67.31 107.31,63.5 MB1.B
N$33
  Top 0.381: T33.3 121.92,67.31 121.92,63.5 MB2.B
N$34
  Top 0.381: T34.3 135.25,67.94 135.89,67.31 135.89,63.5 MB3.B
N$35
  Top 0.381: T35.3 150.5,67.31 150.5,63.5 MB4.B
N$36
  Top 0.381: T36.3 163.83,67.94 164.47,67.31 164.47,63.5 MB5.B
N$37
  Top 0.381: T37.3 179.07,67.31 179.07,63.5 MB6.B
N$38
  Top 0.381: T38.3 192.41,64.14 MB7.B
N$39
  Bottom 0.381: T39.3 207.65,67.31 207.65,63.5 MB8.B
N$40
  Top 0.381: T40.3 220.98,67.94 221.62,67.31 221.62,63.5 MB9.B
N$41
  Top 0.381: T41.3 236.22,67.31 236.22,63.5 MB10.B
N$42
  Top 0.381: T42.3 249.56,67.94 250.19,67.31 250.19,63.5 MB11.B
N$43
  Top 0.381: T43.3 93.34,45.09 93.34,41.27 AC0.B
N$44
  Top 0.381: T44.3 106.68,45.72 107.31,45.09 107.31,41.27 AC1.B
N$45
  Bottom 0.381: T45.3 121.92,45.09 121.92,41.27 AC2.B
N$46
  Top 0.381: T46.3 135.25,45.72 135.89,45.09 135.89,41.27 AC3.B
N$47
  Top 0.381: T47.3 150.5,45.09 150.5,41.27 AC4.B
N$48
  Top 0.381: T48.3 163.83,45.72 164.47,45.09 164.47,41.27 AC5.B
N$49
  Top 0.381: T49.3 179.07,45.09 179.07,41.27 AC6.B
N$50
  Top 0.381: T50.3 192.41,45.72 193.04,45.09 193.04,41.27 AC7.B
N$51
  Top 0.381: T51.3 207.65,45.09 207.65,41.27 AC8.B
N$52
  Top 0.381: T52.3 220.98,45.72 221.62,45.09 221.62,41.27 AC9.B
N$53
  Bottom 0.381: T53.3 236.22,45.09 236.22,41.27 AC10.B
N$54
  Top 0.381: T54.3 250.19,43.81 250.19,41.27 AC11.B
N$55
  Top 0.381: T55.3 92.71,25.4 93.34,24.77 93.34,20.32 MQ0.B
N$56
  Top 0.381: T56.3 106.68,24.77 107.31,24.13 107.31,20.32 MQ1.B
N$57
  Top 0.381: T57.3 121.28,25.4 121.92,24.77 121.92,20.32 MQ2.B
N$58
  Top 0.381: T58.3 135.25,24.77 135.89,24.13 135.89,20.32 MQ3.B
N$59
  Top 0.381: T59.3 149.86,25.4 150.5,24.77 150.5,20.32 MQ4.B
N$60
  Bottom 0.381: T60.3 163.83,24.77 164.47,24.13 164.47,20.32 MQ5.B
N$61
  Top 0.381: T61.3 178.44,25.4 179.07,24.77 179.07,20.32 MQ6.B
N$62
  Bottom 0.381: T62.3 192.41,24.77 193.04,24.13 193.04,20.32 MQ7.B
N$63
  Top 0.381: T63.3 207.01,25.4 207.65,24.77 207.65,20.32 MQ8.B
N$64
  Top 0.381: T64.3 220.98,24.77 221.62,24.13 221.62,20.32 MQ9.B
N$65
  Top 0.381: T65.3 235.59,25.4 236.22,24.77 236.22,20.32 MQ10.B
N$66
  Top 0.381: T66.3 249.56,24.77 250.19,24.13 250.19,20.32 MQ11.B
N$67
  Top 0.381: T67.3 5.08,24.77 5.71,24.13 5.71,20.32 SC0.B
N$68
  Top 0.381: T68.3 19.68,25.4 20.32,24.77 20.32,20.32 SC1.B
N$69
  Bottom 0.381: T69.3 33.66,24.77 34.29,24.13 34.29,20.32 SC2.B
N$70
  Bottom 0.381: T70.3 48.26,25.4 48.9,24.77 48.9,20.32 SC3.B
N$71
  Bottom 0.381: T71.3 62.23,24.77 62.87,24.13 62.87,20.32 SC4.B
N$72
  Top 0.381: T72.3 78.11,45.72 78.74,45.09 78.74,41.27 LINK.B
N$73
  Bottom 0.381: T73.3 357.5,105.41 363.22,105.41 ION.B
N$74
  Bottom 0.381: T74.3 363.22,93.98 363.22,94.61 364.49,95.89 PAUSE.B
N$75
  Top 0.381: T75.3 357.5,83.19 363.22,83.19 RUN.B
N$76
  Bottom 0.381: T76.3 344.17,107.31 FETCH.B
N$77
  Bottom 0.381: T77.3 337.19,96.52 EXECUTE.B
N$78
  Top 0.381: T78.3 344.17,85.09 DEFER.B
N$79
  Bottom 0.381: T79.3 337.19,74.3 WORDCOUNT.B
N$80
  Bottom 0.381: T80.3 344.17,62.87 CURRENTADDRESS.B
N$81
  Bottom 0.381: T81.3 337.19,52.07 BREAK.B
N$82
  Top 0.381: T82.3 315.6,107.31 AND.B
N$83
  Bottom 0.381: T83.3 308.61,96.52 TAD.B
N$84
  Bottom 0.381: T84.3 315.6,85.09 ISZ.B
N$85
  Bottom 0.381: T85.3 308.61,74.3 DCA.B
N$86
  Bottom 0.381: T86.3 315.6,62.87 JMS.B
N$87
  Bottom 0.381: T87.3 308.61,52.07 JMP.B
N$88
  Bottom 0.381: T88.3 315.6,40.64 IOT.B
N$89
  Bottom 0.381: T89.3 308.61,29.84 OPR.B
OPR
  Top 0.381: T89.2 318.13,28.57 329.56,40.01 329.56,128.27 330.2,128.91 F40BOT.11
PAUSE
  Bottom 0.381: T74.2 354.96,95.25 347.98,102.23 334.64,102.23 334.64,123.19 339.73,128.27 F40TOP.17
PC0
  Bottom 0.381: T7.2 107.95,128.91 114.3,128.91 D40TOP.1
PC1
  Top 0.381: T8.2 107.95,114.94 120.65,127.64 D40BOT.5
PC2
  Bottom 0.381: T9.2 121.92,114.94 121.92,128.91 D40TOP.6
PC3
  Top 0.381: T10.2 136.53,114.94 135.25,116.2 135.25,128.91 D40BOT.14
PC4
  Bottom 0.381: T11.2 151.13,114.3 153.03,114.3 154.94,112.39 154.94,68.58 153.03,66.67 140.97,66.67 140.97,100.97 139.06,102.87 139.06,124.46 135.25,128.27 135.25,128.91 D40TOP.14
PC5
  Top 0.381: T12.2 165.1,114.94 155.57,114.94 155.57,116.2 142.88,128.91 D40BOT.19
PC6
  Bottom 0.381: T13.2 193.68,128.91 200.03,128.91 E40TOP.1
PC7
  Top 0.381: T14.2 193.68,114.94 206.38,127.64 E40BOT.5
PC8
  Bottom 0.381: T15.2 207.65,114.94 207.65,128.91 E40TOP.6
PC9
  Top 0.381: T16.2 222.25,111.76 222.88,111.12 225.43,111.12 225.43,118.11 220.98,122.56 220.98,128.91 E40BOT.14
PC10
  Bottom 0.381: E40TOP.14 220.98,128.91 220.98,118.11 223.52,115.57 223.52,114.94 236.22,114.94 T17.2
PC11
  Top 0.381: E40BOT.19 228.6,128.91 242.57,114.94 250.82,114.94 T18.2
RUN
  Bottom 0.381: T75.2 355.6,83.82 355.6,81.92 356.87,80.64 367.03,80.64 367.03,107.95 347.35,127.64 341.63,127.64 341.63,128.91 F40TOP.18
SC0
  Bottom 0.381: T67.2 6.35,27.94 33.66,55.24 33.66,127 34.92,128.27 C40TOP.5
SC1
  Top 0.381: T68.2 20.32,27.3 3.81,43.81 3.81,120.02 12.7,128.91 28.57,128.91 C40BOT.1
SC2
  Bottom 0.381: T69.2 34.92,27.94 47.62,40.64 C40TOP.13
SC3
  Top 0.381: T70.2 48.9,27.3 5.08,71.12 5.08,114.3 6.99,116.2 19.68,116.2 19.68,111.76 20.32,111.12 33.66,111.12 33.66,125.09 36.2,127.64 36.2,128.91 C40BOT.6
SC4
  Bottom 0.381: T71.2 63.5,27.94 67.94,32.38 67.94,116.2 55.88,128.27 55.88,128.91 C40TOP.18
TAD
  Top 0.381: T83.2 318.13,95.25 319.4,96.52 319.4,125.09 316.23,128.27 316.23,128.91 F40BOT.2
WC
  Top 0.381: T79.2 346.71,73.03 349.25,75.56 349.25,118.75 339.73,128.27 F40BOT.17

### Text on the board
Bottom: PDP-8/I Light Board 50045108 | 5404519
tPlace: Transistor and trace placement differs from DEC's.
